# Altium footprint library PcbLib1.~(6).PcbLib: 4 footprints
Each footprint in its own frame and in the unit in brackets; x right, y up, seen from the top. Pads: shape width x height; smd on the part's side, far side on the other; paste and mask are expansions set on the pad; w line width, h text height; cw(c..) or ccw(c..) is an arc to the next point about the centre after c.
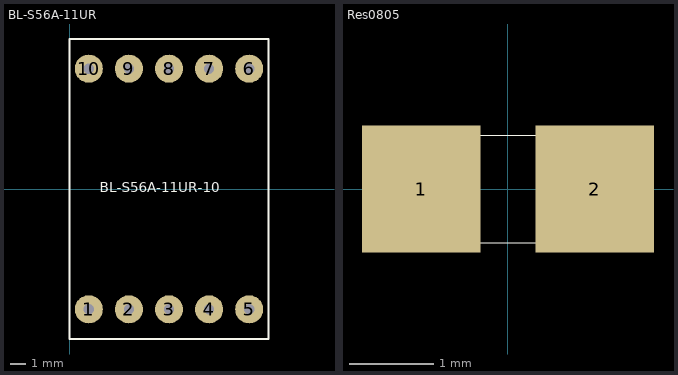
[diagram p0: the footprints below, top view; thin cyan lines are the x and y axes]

## BL-S56A-11UR [mil]
pads (10):
  round 70 hole 25.59: 1(48.03,-300) 2(148.03,-300) 3(248.03,-300) 4(348.03,-300) 5(448.03,-300) 6(448.03,300) 7(348.03,300) 8(248.03,300) 9(148.03,300) 10(48.03,300)
Top Overlay:
  lines w3.94: 496.06,122.05 496.06,374.02 ; 496.06,374.02 0,374.02 0,-374.02 496.06,-374.02 496.06,374.02
  text "BL-S56A-11UR-10" at 75,-8 h25
3D body: height 314.96, standoff 0, extent 0,-374.02 496.06,374.02

## PCBComponent_1 [mil]

## PCBComponent_1 - duplicate [mil]

## Res0805 [mm]
pads (2):
  rect 1.4x1.5 smd: 1(-1.025,0) 2(1.025,0)
Top Overlay:
  lines w0.01: -1.524,-0.635 1.524,-0.635 1.524,0.635 -1.524,0.635 -1.524,-0.635
3D body: height 0.76, standoff 0, extent -1.15,-0.675 1.15,0.675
